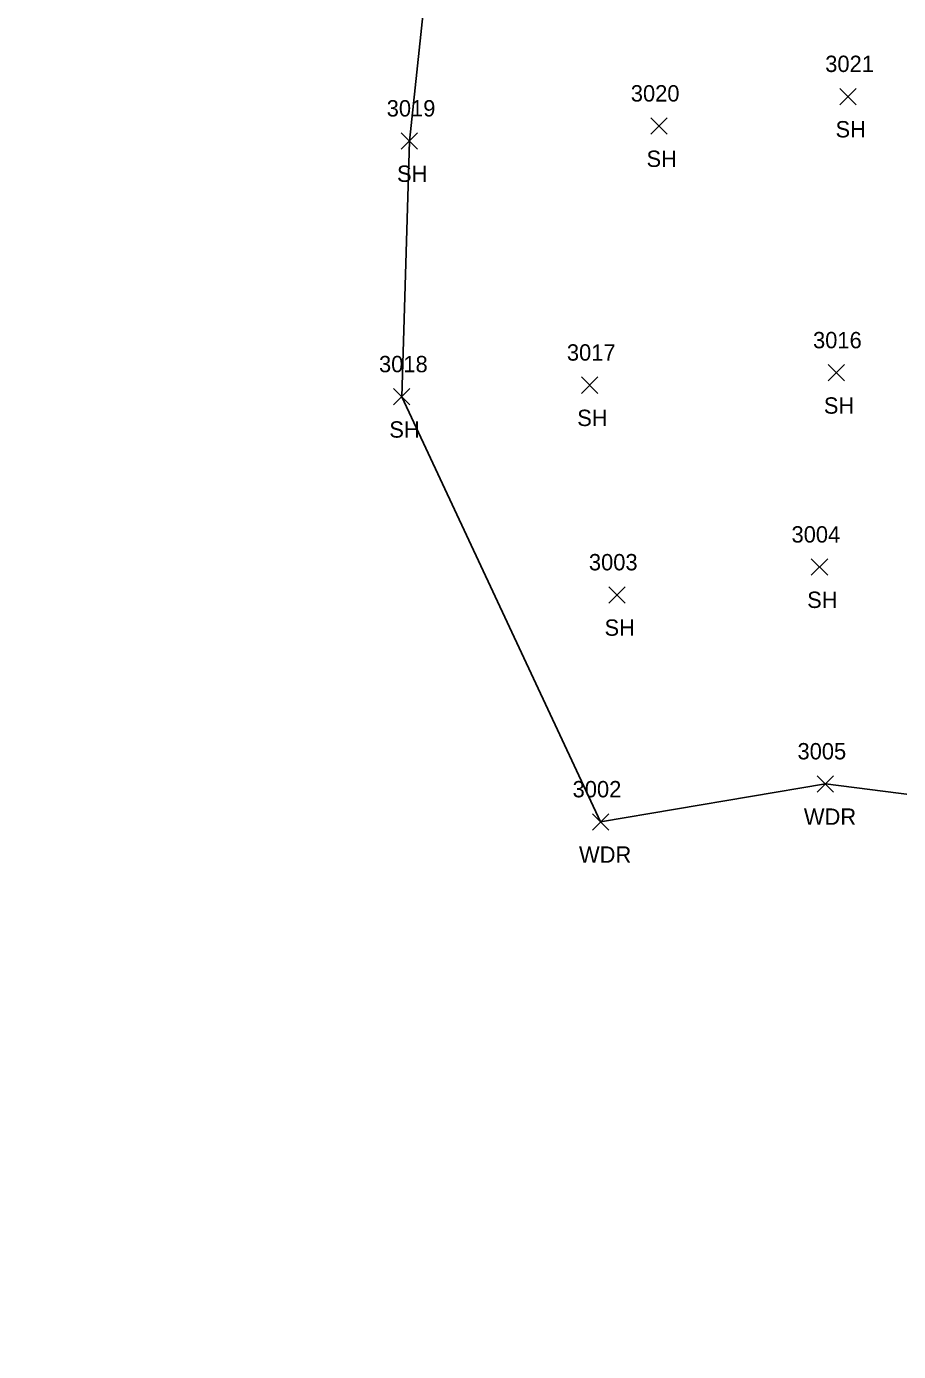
# Model space of a CAD drawing. Extents: x 1509053 to 1511576, y 400838 to 402572.
# Drawn here: x 1509568.7 to 1509675.3, y 401423.4 to 401585.4 of the extents above; entities that cross this region are included whole.
import ezdxf

# ---------------------------------------------------------------- set-up
doc = ezdxf.new("R2010")
doc.units = 0
for name, color, linetype in [('L_A', 7, 'Continuous'), ('L_I', 7, 'Continuous'), ('L_TIC', 7, 'Continuous'), ('LAWA', 7, 'Continuous'), ('LSOGP', 7, 'Continuous')]:
    doc.layers.add(name, color=color, linetype=linetype)

msp = doc.modelspace()

# ---------------------------------------------------------------- linework, layer by layer
at = {"layer": 'L_TIC'}
for points in [[(1509668.1, 401575.84), (1509670.1, 401577.84)], [(1509670.1, 401575.84), (1509668.1, 401577.84)], [(1509645, 401572.23), (1509647, 401574.23)], [(1509647, 401572.23), (1509645, 401574.23)], [(1509614.52, 401570.4), (1509616.52, 401572.4)], [(1509616.52, 401570.4), (1509614.52, 401572.4)], [(1509666.67, 401542.05), (1509668.67, 401544.05)], [(1509668.67, 401542.05), (1509666.67, 401544.05)], [(1509636.53, 401540.54), (1509638.53, 401542.54)], [(1509638.53, 401540.54), (1509636.53, 401542.54)], [(1509613.57, 401539.12), (1509615.57, 401541.12)], [(1509615.57, 401539.12), (1509613.57, 401541.12)], [(1509664.63, 401518.29), (1509666.63, 401520.29)], [(1509666.63, 401518.29), (1509664.63, 401520.29)], [(1509639.87, 401514.89), (1509641.87, 401516.89)], [(1509641.87, 401514.89), (1509639.87, 401516.89)], [(1509665.35, 401491.77), (1509667.35, 401493.77)], [(1509667.35, 401491.77), (1509665.35, 401493.77)], [(1509637.88, 401487.13), (1509639.88, 401489.13)], [(1509639.88, 401487.13), (1509637.88, 401489.13)]]:
    msp.add_lwpolyline(points, dxfattribs=at)
at = {"layer": 'LAWA'}
msp.add_lwpolyline([(1509638.88, 401488.13), (1509666.35, 401492.77), (1509693.47, 401489.31), (1509706.73, 401489.66), (1509714.33, 401510.79), (1509715.13, 401545.88), (1509713.34, 401580.23), (1509712.38, 401615.78), (1509710.87, 401643.63), (1509696.77, 401674.88), (1509690.26, 401693.05), (1509667.45, 401720.56), (1509662.48, 401743.44), (1509649.82, 401764.29), (1509628.65, 401784.18), (1509611.29, 401798.2), (1509592.85, 401815.68), (1509576.11, 401831.25), (1509568.72, 401841.78), (1509569.85, 401855.18), (1509582.24, 401868.06), (1509599.14, 401876.59), (1509619.4, 401883.23)], dxfattribs=at)
at = {"layer": 'LSOGP'}
msp.add_lwpolyline([(1509619.06, 401604.82), (1509615.52, 401571.4), (1509614.57, 401540.12), (1509638.88, 401488.13), (1509666.35, 401492.77), (1509693.47, 401489.31), (1509718.05, 401444.54), (1509718.3, 401438.26), (1509718.5, 401437.3), (1509717.88, 401435.11), (1509718.83, 401433.96), (1509718.39, 401429.02), (1509705.02, 401423.16)], dxfattribs=at)

# ---------------------------------------------------------------- texts
at = {"layer": 'L_A'}
for s, p in [('SH', (1509667.59, 401571.84)), ('SH', (1509644.49, 401568.23)), ('SH', (1509614, 401566.4)), ('SH', (1509666.16, 401538.05)), ('SH', (1509613.06, 401535.12)), ('SH', (1509636.02, 401536.54)), ('SH', (1509664.12, 401514.29)), ('SH', (1509639.36, 401510.89)), ('WDR', (1509663.72, 401487.77)), ('WDR', (1509636.24, 401483.13))]:
    msp.add_text(s, height=2, dxfattribs=at).set_placement(p)
at = {"layer": 'L_I'}
for s, p in [('3021', (1509666.33, 401579.84)), ('3020', (1509642.57, 401576.23)), ('3019', (1509612.74, 401574.4)), ('3016', (1509664.84, 401546.05)), ('3018', (1509611.8, 401543.12)), ('3017', (1509634.76, 401544.54)), ('3004', (1509662.21, 401522.29)), ('3003', (1509637.45, 401518.89)), ('3005', (1509662.94, 401495.77)), ('3002', (1509635.46, 401491.13))]:
    msp.add_text(s, height=2, dxfattribs=at).set_placement(p)

doc.saveas('drawing.dxf')
